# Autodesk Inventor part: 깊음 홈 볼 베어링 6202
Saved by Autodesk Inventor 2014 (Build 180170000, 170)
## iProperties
Created: 2025-06
Part Number: 깊음 홈 볼 베어링 6202
Material: 일반
Document SubType Name: Modeling
Designer: dg
Density: 1 g/cm^3
Appearance: 기본값
Author: dg
Author: jhkim
Description: 깊은 그루브 볼 베어링
Creation Date: 2025-05-27
Sending System: Autodesk Inventor 2026
Preprocessor: ST-DEVELOPER v20.1
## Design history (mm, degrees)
node "깊음 홈 볼 베어링 62021"
body "Solid1"
node "Solid1_1"
node "Solid1_2"
node "Solid1_3"
node "Solid1_4"
node "Solid1_5"
node "Solid1_6"
node "Solid1_7"
node "Solid1_8"
node "Solid1_9"
node "기준1"
node "기준2"
node "기준3"
node "기준4"
node "기준5"
node "기준6"
node "기준7"
node "기준8"
node "기준9"
node "기준10"
